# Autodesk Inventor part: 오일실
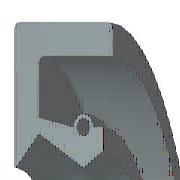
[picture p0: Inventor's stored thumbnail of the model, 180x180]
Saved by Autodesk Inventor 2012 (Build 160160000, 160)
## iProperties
IsCustomPart: 0
Manager: KYOUNG IL JANG
Company: 한국ATC센터
Created: 2009-02
Part Number: 오일실
Material: 고무
Description: 오일-실
Document SubType Name: Modeling
Standard: KS B 2804
Standards Organization: KS
Language: ko-KR
Size Designation: D - 20 35 8
Categories: <MemberInstance><Categories><Category DisplayName="샤프트 부품" InternalName="7f7aeb1f-a693-4053-b835-cee3144e0d98" Mnemonic="SHFT"><Category DisplayName="실링" Intern
Density: 0.93 g/cm^3
Checked By: KYOUNG IL JANG
Vendor: CBT Solutions
Designer: KYOUNG IL JANG
Author: KYOUNG IL JANG
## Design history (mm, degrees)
revolve "본체" stored, may be unused: angle "d17" = 90 deg
revolve "스프링1" stored, may be unused: angle "d18" = 90 deg
body "Solid1"
sketch "스케치1"
  geometry: L1 (0, 17.5)-(8, 17.5); L2 (8, 15.75)-(1.75, 15.75); L3 (1.75, 11.75)-(4.9, 10); L4 (4.9, 10)-(0, 10); L5 (0, 0)-(9.586, 0) reference; L6 (4.9, 10)-(6.3, 10.875); L7 (0, 18)-(0, -3) reference; L8 (-1.941, 0)-(11.507, 0) reference; L9 (4.2, 12.1)-(1.75, 12.71); L10 (1.75, 12.71)-(1.75, 15.75); L11 (0, 17.5)-(0, 10.088); L12 (4.9, 10)-(0, 10); L13 (1.75, 11.75)-(0.152, 10.028); L14 (8, 17.5)-(8, 15.75); L15 (5.6, 12.1)-(6.3, 12.1); L16 (6.3, 12.1)-(6.3, 10.875); C1 r 0.455 at (4.9, 12.1); A1 r 0.7 centre (4.9, 12.1) between (5.6, 12.1) and (4.2, 12.1); A2 r 0.088 centre (0.088, 10.088) between (0, 10.088) and (0.152, 10.028); 1 further point
  constraints: 28 end point, 5 horizontal alignment, 5 point on line, 4 point on circle, 4 vertical alignment, 3 centre point, 3 tangent, 2 collinear, 2 horizontal, 2 perpendicular, 1 coincident, 1 parallel
  dimensions: "d0" = 35 diameter of L1 L5 (= SD2); "d1" = 1.75 distance of L1.end L2.start (= SD); "d2" = 0.91 diameter of C1 (= SPDI); "d3" = 1.4 diameter of A1 (= SPDA); "d4" = 20 diameter of L3.end L5 (= NND); "d5" = 23.5 diameter of L3.start L5 (= TKDM); "d7" = 25.42 diameter of L9.end L5 (= TKDM + 0.24 x SWDT); "d8" = 1.75 distance between parallel lines of L11 L10 (= SD); "d9" = 4.9 distance from line of L11 C1.centre (= SPDST); "d10" = 24.2 diameter of C1.centre L5 (= HLDM); "d11" = 0.0875 radius of A2 (= 0.25 x LAB); "d12" = 6.3 distance between parallel lines of L11 L16 (= SDI); "d13" = 21.75 diameter of L6.end L5 (= ABDM); "d14" = 8 distance from line of L11 L1.end (= SWDT)
fillet "모깎기1" dims "d6" = 0.3 (= RR)
other parameters: "SD2" = 35 [user parameter; used in 1 equation term], "SWDT" = 8 [user parameter; used in 2 equation terms], "RR" = 0.3 [user parameter; used in 1 equation term], "SD" = 1.75 [user parameter; used in 2 equation terms], "NND" = 20 [user parameter; used in 1 equation term], "SPDA" = 1.4 [user parameter; used in 1 equation term], "SPDI" = 0.91 [user parameter; used in 1 equation term], "TKDM" = 23.5 [user parameter; used in 2 equation terms], "HLDM" = 24.2 [user parameter; used in 1 equation term], "ABDM" = 21.75 [user parameter; used in 1 equation term], "SDI" = 6.3 [user parameter; used in 1 equation term], "SPDST" = 4.9 [user parameter; used in 1 equation term], "LAB" = 0.35 [user parameter; used in 1 equation term], "d15" = 0, "d16" = 0, "d19" = 0
